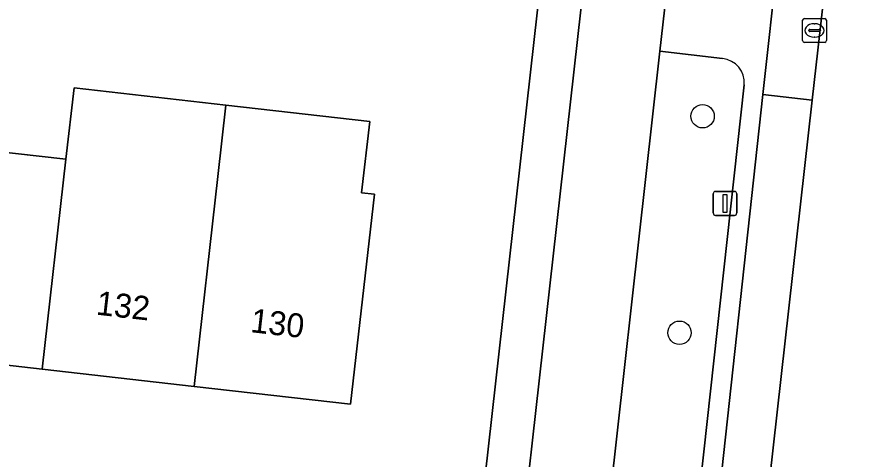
# Model space of a CAD drawing. Extents: x 162026 to 163502, y 387295 to 388169.
# Drawn here: x 162277.28 to 162312.4, y 388004.25 to 388022.74 of the extents above; entities that cross this region are included whole.
import ezdxf

# ---------------------------------------------------------------- set-up
doc = ezdxf.new("R2010")
doc.units = 0
for name, color, linetype in [('IMGEO_Berm_groen', 7, 'Continuous'), ('IMGEO_Boom', 7, 'Continuous'), ('IMGEO_Erf', 7, 'Continuous'), ('IMGEO_Fietspad_gesloten', 7, 'Continuous'), ('IMGEO_Kolk', 7, 'Continuous'), ('IMGEO_Lichtmast', 7, 'Continuous'), ('IMGEO_Pand', 7, 'Continuous'), ('IMGEO_Pand_nummerreeks', 7, 'Continuous'), ('IMGEO_Parkeervlak_open', 7, 'Continuous'), ('IMGEO_Rijbaan_lokaal_gesloten', 7, 'Continuous'), ('IMGEO_Voetpad_open', 7, 'Continuous')]:
    doc.layers.add(name, color=color, linetype=linetype)

msp = doc.modelspace()

# ---------------------------------------------------------------- linework, layer by layer
at = {"layer": 'IMGEO_Berm_groen'}
for points in [[(162306.805, 388021), (162304.186, 388021.301), (162301.519, 387997.48), (162304.295, 387997.152)], [(162305.313, 387998.09), (162307.717, 388019.902)]]:
    msp.add_lwpolyline(points, dxfattribs=at)
msp.add_arc((162306.698, 388019.983), 1.022, 355.4284, 83.9977, dxfattribs=at)
at = {"layer": 'IMGEO_Boom'}
for centre in [(162305.972, 388018.587), (162305.006, 388009.536)]:
    msp.add_circle(centre, 0.489, dxfattribs=at)
at = {"layer": 'IMGEO_Erf'}
msp.add_lwpolyline([(162296.578, 388000.949), (162299.337, 388025.532)], dxfattribs=at)
msp.add_lwpolyline([(162279.335, 388016.79), (162279.673, 388019.771), (162286.03, 388019.05), (162292.043, 388018.368), (162291.704, 388015.385), (162292.241, 388015.324), (162291.244, 388006.545), (162284.696, 388007.289), (162278.339, 388008.01), (162271.878, 388008.744), (162265.433, 388009.476), (162266.429, 388018.255), (162272.875, 388017.523)], close=True, dxfattribs=at)
at = {"layer": 'IMGEO_Fietspad_gesloten'}
msp.add_lwpolyline([(162312.231, 388124.755), (162304.655, 388056.674), (162296.82, 387986.925), (162300.294, 387986.533), (162301.519, 387997.48), (162304.186, 388021.301), (162304.64, 388025.356), (162307.493, 388050.846), (162307.76, 388053.225), (162311.074, 388082.834), (162311.087, 388082.949), (162311.344, 388085.243), (162314.298, 388111.617), (162314.566, 388114.013), (162315.606, 388123.294)], dxfattribs=at)
at = {"layer": 'IMGEO_Kolk'}
for p, q in [((162310.154, 388021.748), (162310.154, 388022.6)), ((162310.229, 388022.674), (162311.081, 388022.674)), ((162311.155, 388022.6), (162311.155, 388021.748)), ((162310.642, 388022.454), (162310.667, 388022.454)), ((162310.413, 388022.168), (162310.413, 388022.18)), ((162310.851, 388022.131), (162310.453, 388022.131)), ((162310.456, 388022.217), (162310.854, 388022.217)), ((162310.665, 388021.894), (162310.64, 388021.894)), ((162310.897, 388022.18), (162310.897, 388022.168)), ((162311.081, 388021.674), (162310.229, 388021.674))]:
    msp.add_line(p, q, dxfattribs=at)
for points in [[(162310.154, 388021.748), (162310.154, 388022.6)], [(162310.229, 388022.674), (162311.081, 388022.674)], [(162311.155, 388022.6), (162311.155, 388021.748)], [(162311.081, 388021.674), (162310.229, 388021.674)]]:
    msp.add_lwpolyline(points, dxfattribs=at)
for centre, radius, start, end in [((162310.231, 388022.598), 0.0765, 91.552, 178.448), ((162310.231, 388022.598), 0.0765, 91.552, 178.448), ((162311.079, 388022.598), 0.0765, 1.552, 88.448), ((162311.079, 388022.598), 0.0765, 1.552, 88.448), ((162310.453, 388022.177), 0.0403, 85.8775, 175.7526), ((162310.45, 388022.167), 0.0366, 178.938, 274.7102), ((162310.854, 388022.174), 0.043, 264.8664, 352.4533), ((162310.858, 388022.179), 0.0386, 1.7309, 96.639), ((162310.231, 388021.75), 0.0765, 181.552, 268.448), ((162310.231, 388021.75), 0.0765, 181.552, 268.448), ((162311.079, 388021.75), 0.0765, 271.552, 358.448), ((162311.079, 388021.75), 0.0765, 271.552, 358.448)]:
    msp.add_arc(centre, radius, start, end, dxfattribs=at)
for centre, major_axis, ratio, start_param, end_param in [((162310.641, 388022.174), (-0.387, 0.002), 0.722429, 4.712389, 7.853982), ((162310.666, 388022.174), (-0.39, 0.002), 0.717154, 1.570796, 4.712389)]:
    msp.add_ellipse(centre, major_axis=major_axis, ratio=ratio, start_param=start_param, end_param=end_param, dxfattribs=at)
at = {"layer": 'IMGEO_Lichtmast'}
for p, q in [((162306.413, 388014.541), (162306.413, 388015.341)), ((162306.413, 388015.341), (162306.413, 388014.541)), ((162306.513, 388015.441), (162307.303, 388015.441)), ((162307.303, 388015.441), (162306.513, 388015.441)), ((162307.403, 388015.341), (162307.403, 388014.541)), ((162307.403, 388014.541), (162307.403, 388015.341)), ((162307.303, 388014.441), (162306.513, 388014.441)), ((162306.513, 388014.441), (162307.303, 388014.441))]:
    msp.add_line(p, q, dxfattribs=at)
msp.add_lwpolyline([(162306.833, 388015.316), (162306.983, 388015.316), (162306.983, 388014.566), (162306.833, 388014.566), (162306.833, 388015.316)], dxfattribs=at)
for centre, start, end in [((162306.513, 388015.341), 90, 180), ((162306.513, 388015.341), 90, 180), ((162307.303, 388015.341), 0, 90), ((162307.303, 388015.341), 360, 90), ((162306.513, 388014.541), 180, 270), ((162306.513, 388014.541), 180, 270), ((162307.303, 388014.541), 270, 0), ((162307.303, 388014.541), 270, 0)]:
    msp.add_arc(centre, 0.1, start, end, dxfattribs=at)
at = {"layer": 'IMGEO_Pand'}
for points in [[(162285.692, 388016.068), (162286.03, 388019.05), (162279.673, 388019.771), (162279.335, 388016.79), (162278.339, 388008.01), (162284.696, 388007.289)], [(162292.241, 388015.324), (162291.704, 388015.385), (162292.043, 388018.368), (162286.03, 388019.05), (162285.692, 388016.068), (162284.696, 388007.289), (162291.244, 388006.545)], [(162279.335, 388016.79), (162272.875, 388017.523), (162271.878, 388008.744), (162278.339, 388008.01)]]:
    msp.add_lwpolyline(points, close=True, dxfattribs=at)
at = {"layer": 'IMGEO_Parkeervlak_open'}
for points in [[(162310.561, 388019.262), (162308.495, 388019.494), (162306.379, 388000.175)], [(162308.286, 387999.012), (162310.561, 388019.262)]]:
    msp.add_lwpolyline(points, dxfattribs=at)
at = {"layer": 'IMGEO_Rijbaan_lokaal_gesloten'}
msp.add_lwpolyline([(162322.928, 388132.872), (162322.654, 388130.399), (162322.33, 388127.341), (162316.573, 388072.788), (162311.197, 388024.928), (162310.561, 388019.262), (162308.286, 387999.012), (162313.781, 387998.425), (162316.059, 388019.229), (162316.68, 388024.895), (162320.461, 388059.412), (162325.891, 388108.842), (162326.489, 388114.286), (162327.854, 388126.713), (162328.48, 388132.214)], dxfattribs=at)
at = {"layer": 'IMGEO_Voetpad_open'}
for points in [[(162312.631, 388126.808), (162315.776, 388136.387), (162315.326, 388136.551), (162314.337, 388137.776), (162311.776, 388138.06), (162311.157, 388133.023), (162308.965, 388111.891), (162308.786, 388110.273), (162303.064, 388058.749), (162299.499, 388026.976), (162299.337, 388025.532), (162296.578, 388000.949), (162295.808, 387994.688)], [(162306.379, 388000.175), (162308.495, 388019.494), (162309.116, 388025.162), (162314.339, 388072.852), (162320.247, 388126.635)], [(162294.16, 387987.809), (162294.103, 387987.216), (162296.82, 387986.925), (162304.655, 388056.674), (162312.231, 388124.755)], [(162307.253, 388025.081), (162304.64, 388025.356), (162304.186, 388021.301), (162306.805, 388021)], [(162307.717, 388019.902), (162305.313, 387998.09)]]:
    msp.add_lwpolyline(points, dxfattribs=at)
msp.add_lwpolyline([(162311.197, 388024.928), (162309.116, 388025.162), (162308.495, 388019.494), (162310.561, 388019.262)], close=True, dxfattribs=at)
msp.add_arc((162306.698, 388019.983), 1.022, 355.4284, 83.9977, dxfattribs=at)

# ---------------------------------------------------------------- texts
at = {"layer": 'IMGEO_Pand_nummerreeks'}
for s, p in [('132', (162280.569, 388010.295)), ('130', (162287.028, 388009.561))]:
    msp.add_text(s, height=1, rotation=353.5198, dxfattribs=at).set_placement(p)

doc.saveas('drawing.dxf')
